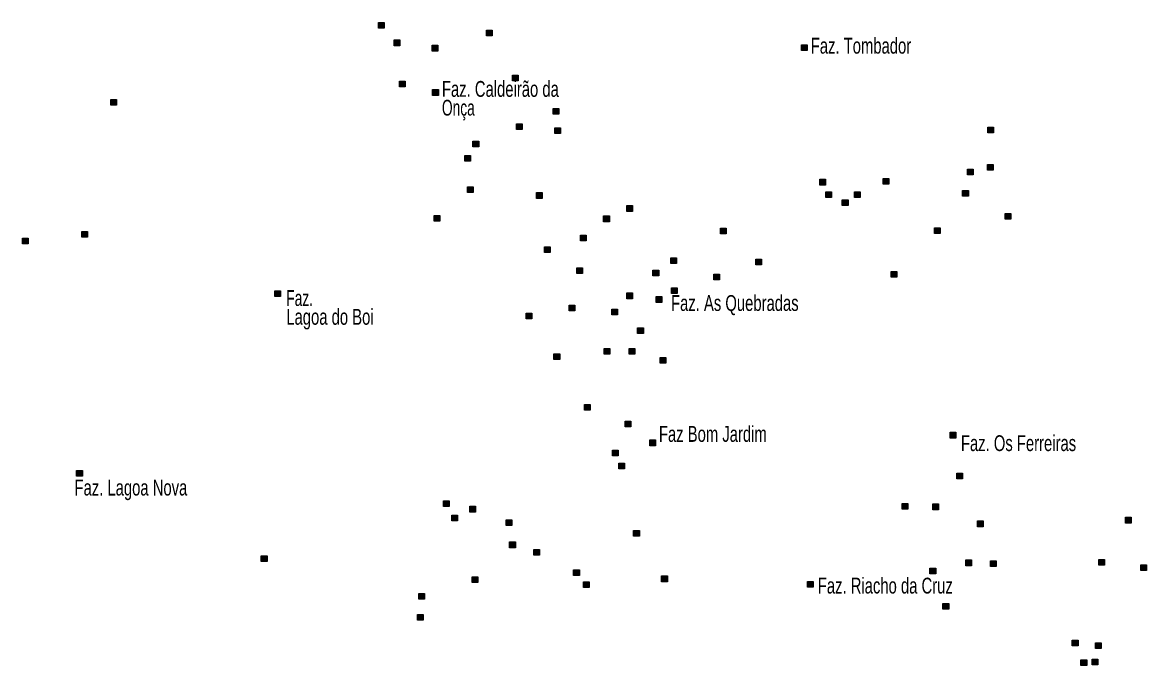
# Model space of a CAD drawing. Extents: x 445.4 to 500, y 8728.7 to 8784.
# Drawn here: x 458.24 to 469.61, y 8757.95 to 8764.45 of the extents above; entities that cross this region are included whole.
import ezdxf
from ezdxf.enums import TextEntityAlignment as Align

# ---------------------------------------------------------------- set-up
doc = ezdxf.new("R2010")
doc.units = 0
doc.header["$LTSCALE"] = 0.064
doc.layers.add('2', color=7, linetype='Continuous', lineweight=25)
doc.layers.add('61', color=7, linetype='Continuous')

msp = doc.modelspace()

# ---------------------------------------------------------------- hatches: boundary and pattern name
at = {"layer": '2'}
for points in [[(461.8411, 8764.4531), (461.8991, 8764.4531), (461.8991, 8764.3951), (461.8411, 8764.3951)], [(462.9316, 8764.3761), (462.9896, 8764.3761), (462.9896, 8764.3181), (462.9316, 8764.3181)], [(461.9995, 8764.2765), (462.0575, 8764.2765), (462.0575, 8764.2185), (461.9995, 8764.2185)], [(462.3841, 8764.2222), (462.4421, 8764.2222), (462.4421, 8764.1642), (462.3841, 8764.1642)], [(466.1186, 8764.2285), (466.1766, 8764.2285), (466.1766, 8764.1705), (466.1186, 8764.1705)], [(462.0538, 8763.86), (462.1118, 8763.86), (462.1118, 8763.802), (462.0538, 8763.802)], [(463.196, 8763.9203), (463.254, 8763.9203), (463.254, 8763.8623), (463.196, 8763.8623)], [(462.3886, 8763.774), (462.4466, 8763.774), (462.4466, 8763.716), (462.3886, 8763.716)], [(459.1351, 8763.6754), (459.1931, 8763.6754), (459.1931, 8763.6174), (459.1351, 8763.6174)], [(463.6059, 8763.5838), (463.6639, 8763.5838), (463.6639, 8763.5258), (463.6059, 8763.5258)], [(463.2348, 8763.4299), (463.2928, 8763.4299), (463.2928, 8763.3719), (463.2348, 8763.3719)], [(463.624, 8763.3891), (463.682, 8763.3891), (463.682, 8763.3311), (463.624, 8763.3311)], [(468.0027, 8763.3944), (468.0607, 8763.3944), (468.0607, 8763.3364), (468.0027, 8763.3364)], [(462.7959, 8763.2533), (462.8539, 8763.2533), (462.8539, 8763.1953), (462.7959, 8763.1953)], [(462.7144, 8763.1084), (462.7724, 8763.1084), (462.7724, 8763.0504), (462.7144, 8763.0504)], [(467.7974, 8762.9716), (467.8554, 8762.9716), (467.8554, 8762.9136), (467.7974, 8762.9136)], [(467.9989, 8763.0171), (468.0569, 8763.0171), (468.0569, 8762.9591), (467.9989, 8762.9591)], [(466.3042, 8762.8675), (466.3622, 8762.8675), (466.3622, 8762.8095), (466.3042, 8762.8095)], [(466.9422, 8762.8765), (467.0002, 8762.8765), (467.0002, 8762.8185), (466.9422, 8762.8185)], [(462.7416, 8762.7915), (462.7996, 8762.7915), (462.7996, 8762.7335), (462.7416, 8762.7335)], [(463.4384, 8762.7327), (463.4964, 8762.7327), (463.4964, 8762.6747), (463.4384, 8762.6747)], [(466.363, 8762.7407), (466.421, 8762.7407), (466.421, 8762.6827), (466.363, 8762.6827)], [(466.6526, 8762.7407), (466.7106, 8762.7407), (466.7106, 8762.6827), (466.6526, 8762.6827)], [(467.7476, 8762.7543), (467.8056, 8762.7543), (467.8056, 8762.6963), (467.7476, 8762.6963)], [(464.3525, 8762.6014), (464.4105, 8762.6014), (464.4105, 8762.5434), (464.3525, 8762.5434)], [(466.5304, 8762.6592), (466.5884, 8762.6592), (466.5884, 8762.6012), (466.5304, 8762.6012)], [(462.4022, 8762.5018), (462.4602, 8762.5018), (462.4602, 8762.4438), (462.4022, 8762.4438)], [(464.1172, 8762.4972), (464.1752, 8762.4972), (464.1752, 8762.4392), (464.1172, 8762.4392)], [(468.1775, 8762.5234), (468.2355, 8762.5234), (468.2355, 8762.4654), (468.1775, 8762.4654)], [(465.2996, 8762.374), (465.3576, 8762.374), (465.3576, 8762.316), (465.2996, 8762.316)], [(467.4626, 8762.3785), (467.5206, 8762.3785), (467.5206, 8762.3205), (467.4626, 8762.3205)], [(458.2411, 8762.2739), (458.2991, 8762.2739), (458.2991, 8762.2159), (458.2411, 8762.2159)], [(458.841, 8762.3398), (458.899, 8762.3398), (458.899, 8762.2818), (458.841, 8762.2818)], [(463.8819, 8762.3025), (463.9399, 8762.3025), (463.9399, 8762.2445), (463.8819, 8762.2445)], [(463.519, 8762.1861), (463.577, 8762.1861), (463.577, 8762.1281), (463.519, 8762.1281)], [(464.7961, 8762.0752), (464.8541, 8762.0752), (464.8541, 8762.0172), (464.7961, 8762.0172)], [(465.6571, 8762.0616), (465.7151, 8762.0616), (465.7151, 8762.0036), (465.6571, 8762.0036)], [(463.8457, 8761.972), (463.9037, 8761.972), (463.9037, 8761.914), (463.8457, 8761.914)], [(464.6163, 8761.9484), (464.6743, 8761.9484), (464.6743, 8761.8904), (464.6163, 8761.8904)], [(465.2317, 8761.9077), (465.2897, 8761.9077), (465.2897, 8761.8497), (465.2317, 8761.8497)], [(467.0236, 8761.9348), (467.0816, 8761.9348), (467.0816, 8761.8768), (467.0236, 8761.8768)], [(460.7913, 8761.7411), (460.8493, 8761.7411), (460.8493, 8761.6831), (460.7913, 8761.6831)], [(464.3525, 8761.7185), (464.4105, 8761.7185), (464.4105, 8761.6605), (464.3525, 8761.6605)], [(464.648, 8761.6813), (464.706, 8761.6813), (464.706, 8761.6233), (464.648, 8761.6233)], [(464.8019, 8761.7719), (464.8599, 8761.7719), (464.8599, 8761.7139), (464.8019, 8761.7139)], [(463.7688, 8761.5963), (463.8268, 8761.5963), (463.8268, 8761.5383), (463.7688, 8761.5383)], [(464.1986, 8761.5555), (464.2566, 8761.5555), (464.2566, 8761.4975), (464.1986, 8761.4975)], [(463.3344, 8761.5148), (463.3924, 8761.5148), (463.3924, 8761.4568), (463.3344, 8761.4568)], [(464.4611, 8761.3654), (464.5191, 8761.3654), (464.5191, 8761.3074), (464.4611, 8761.3074)], [(463.6149, 8761.1028), (463.6729, 8761.1028), (463.6729, 8761.0448), (463.6149, 8761.0448)], [(464.1217, 8761.1571), (464.1797, 8761.1571), (464.1797, 8761.0991), (464.1217, 8761.0991)], [(464.3751, 8761.1571), (464.4331, 8761.1571), (464.4331, 8761.0991), (464.3751, 8761.0991)], [(464.6891, 8761.0658), (464.7471, 8761.0658), (464.7471, 8761.0078), (464.6891, 8761.0078)], [(463.9226, 8760.5912), (463.9806, 8760.5912), (463.9806, 8760.5332), (463.9226, 8760.5332)], [(464.3344, 8760.4237), (464.3924, 8760.4237), (464.3924, 8760.3657), (464.3344, 8760.3657)], [(467.6209, 8760.3095), (467.6789, 8760.3095), (467.6789, 8760.2515), (467.6209, 8760.2515)], [(464.5847, 8760.2325), (464.6427, 8760.2325), (464.6427, 8760.1745), (464.5847, 8760.1745)], [(464.2077, 8760.1294), (464.2657, 8760.1294), (464.2657, 8760.0714), (464.2077, 8760.0714)], [(464.271, 8759.9981), (464.329, 8759.9981), (464.329, 8759.9401), (464.271, 8759.9401)], [(458.7884, 8759.9239), (458.8464, 8759.9239), (458.8464, 8759.8659), (458.7884, 8759.8659)], [(467.6888, 8759.8975), (467.7468, 8759.8975), (467.7468, 8759.8395), (467.6888, 8759.8395)], [(462.4972, 8759.6178), (462.5552, 8759.6178), (462.5552, 8759.5598), (462.4972, 8759.5598)], [(462.7642, 8759.5617), (462.8222, 8759.5617), (462.8222, 8759.5037), (462.7642, 8759.5037)], [(467.1368, 8759.5896), (467.1948, 8759.5896), (467.1948, 8759.5316), (467.1368, 8759.5316)], [(467.4445, 8759.5851), (467.5025, 8759.5851), (467.5025, 8759.5271), (467.4445, 8759.5271)], [(462.5832, 8759.4711), (462.6412, 8759.4711), (462.6412, 8759.4131), (462.5832, 8759.4131)], [(463.1307, 8759.4259), (463.1887, 8759.4259), (463.1887, 8759.3679), (463.1307, 8759.3679)], [(467.897, 8759.4131), (467.955, 8759.4131), (467.955, 8759.3551), (467.897, 8759.3551)], [(469.3948, 8759.4503), (469.4528, 8759.4503), (469.4528, 8759.3923), (469.3948, 8759.3923)], [(464.4204, 8759.3172), (464.4784, 8759.3172), (464.4784, 8759.2592), (464.4204, 8759.2592)], [(463.1669, 8759.2012), (463.2249, 8759.2012), (463.2249, 8759.1432), (463.1669, 8759.1432)], [(460.6556, 8759.0609), (460.7136, 8759.0609), (460.7136, 8759.0029), (460.6556, 8759.0029)], [(463.4113, 8759.1243), (463.4693, 8759.1243), (463.4693, 8759.0663), (463.4113, 8759.0663)], [(467.4173, 8758.9377), (467.4753, 8758.9377), (467.4753, 8758.8797), (467.4173, 8758.8797)], [(467.7793, 8759.0192), (467.8373, 8759.0192), (467.8373, 8758.9612), (467.7793, 8758.9612)], [(468.0282, 8759.0101), (468.0862, 8759.0101), (468.0862, 8758.9521), (468.0282, 8758.9521)], [(469.1233, 8759.0247), (469.1813, 8759.0247), (469.1813, 8758.9667), (469.1233, 8758.9667)], [(469.5486, 8758.9703), (469.6066, 8758.9703), (469.6066, 8758.9123), (469.5486, 8758.9123)], [(462.7868, 8758.8481), (462.8448, 8758.8481), (462.8448, 8758.7901), (462.7868, 8758.7901)], [(463.814, 8758.9205), (463.872, 8758.9205), (463.872, 8758.8625), (463.814, 8758.8625)], [(464.7041, 8758.8572), (464.7621, 8758.8572), (464.7621, 8758.7992), (464.7041, 8758.7992)], [(463.9136, 8758.7983), (463.9716, 8758.7983), (463.9716, 8758.7403), (463.9136, 8758.7403)], [(466.1775, 8758.8018), (466.2355, 8758.8018), (466.2355, 8758.7438), (466.1775, 8758.7438)], [(462.2484, 8758.6806), (462.3064, 8758.6806), (462.3064, 8758.6226), (462.2484, 8758.6226)], [(467.5485, 8758.58), (467.6065, 8758.58), (467.6065, 8758.522), (467.5485, 8758.522)], [(462.2348, 8758.4678), (462.2928, 8758.4678), (462.2928, 8758.4098), (462.2348, 8758.4098)], [(468.8563, 8758.2097), (468.9143, 8758.2097), (468.9143, 8758.1517), (468.8563, 8758.1517)], [(469.0916, 8758.1826), (469.1496, 8758.1826), (469.1496, 8758.1246), (469.0916, 8758.1246)], [(468.9439, 8758.0098), (469.0019, 8758.0098), (469.0019, 8757.9518), (468.9439, 8757.9518)], [(469.0554, 8758.0151), (469.1134, 8758.0151), (469.1134, 8757.9571), (469.0554, 8757.9571)]]:
    msp.add_hatch(color=256, dxfattribs=at).paths.add_polyline_path(points)

# ---------------------------------------------------------------- linework, layer by layer
for points in [[(461.8411, 8764.4531), (461.8991, 8764.4531), (461.8991, 8764.3951), (461.8411, 8764.3951)], [(462.9316, 8764.3761), (462.9896, 8764.3761), (462.9896, 8764.3181), (462.9316, 8764.3181)], [(461.9995, 8764.2765), (462.0575, 8764.2765), (462.0575, 8764.2185), (461.9995, 8764.2185)], [(462.3841, 8764.2222), (462.4421, 8764.2222), (462.4421, 8764.1642), (462.3841, 8764.1642)], [(466.1186, 8764.2285), (466.1766, 8764.2285), (466.1766, 8764.1705), (466.1186, 8764.1705)], [(462.0538, 8763.86), (462.1118, 8763.86), (462.1118, 8763.802), (462.0538, 8763.802)], [(463.196, 8763.9203), (463.254, 8763.9203), (463.254, 8763.8623), (463.196, 8763.8623)], [(462.3886, 8763.774), (462.4466, 8763.774), (462.4466, 8763.716), (462.3886, 8763.716)], [(459.1351, 8763.6754), (459.1931, 8763.6754), (459.1931, 8763.6174), (459.1351, 8763.6174)], [(463.6059, 8763.5838), (463.6639, 8763.5838), (463.6639, 8763.5258), (463.6059, 8763.5258)], [(463.2348, 8763.4299), (463.2928, 8763.4299), (463.2928, 8763.3719), (463.2348, 8763.3719)], [(463.624, 8763.3891), (463.682, 8763.3891), (463.682, 8763.3311), (463.624, 8763.3311)], [(468.0027, 8763.3944), (468.0607, 8763.3944), (468.0607, 8763.3364), (468.0027, 8763.3364)], [(462.7959, 8763.2533), (462.8539, 8763.2533), (462.8539, 8763.1953), (462.7959, 8763.1953)], [(462.7144, 8763.1084), (462.7724, 8763.1084), (462.7724, 8763.0504), (462.7144, 8763.0504)], [(467.7974, 8762.9716), (467.8554, 8762.9716), (467.8554, 8762.9136), (467.7974, 8762.9136)], [(467.9989, 8763.0171), (468.0569, 8763.0171), (468.0569, 8762.9591), (467.9989, 8762.9591)], [(466.3042, 8762.8675), (466.3622, 8762.8675), (466.3622, 8762.8095), (466.3042, 8762.8095)], [(466.9422, 8762.8765), (467.0002, 8762.8765), (467.0002, 8762.8185), (466.9422, 8762.8185)], [(462.7416, 8762.7915), (462.7996, 8762.7915), (462.7996, 8762.7335), (462.7416, 8762.7335)], [(463.4384, 8762.7327), (463.4964, 8762.7327), (463.4964, 8762.6747), (463.4384, 8762.6747)], [(466.363, 8762.7407), (466.421, 8762.7407), (466.421, 8762.6827), (466.363, 8762.6827)], [(466.6526, 8762.7407), (466.7106, 8762.7407), (466.7106, 8762.6827), (466.6526, 8762.6827)], [(467.7476, 8762.7543), (467.8056, 8762.7543), (467.8056, 8762.6963), (467.7476, 8762.6963)], [(464.3525, 8762.6014), (464.4105, 8762.6014), (464.4105, 8762.5434), (464.3525, 8762.5434)], [(466.5304, 8762.6592), (466.5884, 8762.6592), (466.5884, 8762.6012), (466.5304, 8762.6012)], [(462.4022, 8762.5018), (462.4602, 8762.5018), (462.4602, 8762.4438), (462.4022, 8762.4438)], [(464.1172, 8762.4972), (464.1752, 8762.4972), (464.1752, 8762.4392), (464.1172, 8762.4392)], [(468.1775, 8762.5234), (468.2355, 8762.5234), (468.2355, 8762.4654), (468.1775, 8762.4654)], [(465.2996, 8762.374), (465.3576, 8762.374), (465.3576, 8762.316), (465.2996, 8762.316)], [(467.4626, 8762.3785), (467.5206, 8762.3785), (467.5206, 8762.3205), (467.4626, 8762.3205)], [(458.2411, 8762.2739), (458.2991, 8762.2739), (458.2991, 8762.2159), (458.2411, 8762.2159)], [(458.841, 8762.3398), (458.899, 8762.3398), (458.899, 8762.2818), (458.841, 8762.2818)], [(463.8819, 8762.3025), (463.9399, 8762.3025), (463.9399, 8762.2445), (463.8819, 8762.2445)], [(463.519, 8762.1861), (463.577, 8762.1861), (463.577, 8762.1281), (463.519, 8762.1281)], [(464.7961, 8762.0752), (464.8541, 8762.0752), (464.8541, 8762.0172), (464.7961, 8762.0172)], [(465.6571, 8762.0616), (465.7151, 8762.0616), (465.7151, 8762.0036), (465.6571, 8762.0036)], [(463.8457, 8761.972), (463.9037, 8761.972), (463.9037, 8761.914), (463.8457, 8761.914)], [(464.6163, 8761.9484), (464.6743, 8761.9484), (464.6743, 8761.8904), (464.6163, 8761.8904)], [(465.2317, 8761.9077), (465.2897, 8761.9077), (465.2897, 8761.8497), (465.2317, 8761.8497)], [(467.0236, 8761.9348), (467.0816, 8761.9348), (467.0816, 8761.8768), (467.0236, 8761.8768)], [(460.7913, 8761.7411), (460.8493, 8761.7411), (460.8493, 8761.6831), (460.7913, 8761.6831)], [(464.3525, 8761.7185), (464.4105, 8761.7185), (464.4105, 8761.6605), (464.3525, 8761.6605)], [(464.648, 8761.6813), (464.706, 8761.6813), (464.706, 8761.6233), (464.648, 8761.6233)], [(464.8019, 8761.7719), (464.8599, 8761.7719), (464.8599, 8761.7139), (464.8019, 8761.7139)], [(463.7688, 8761.5963), (463.8268, 8761.5963), (463.8268, 8761.5383), (463.7688, 8761.5383)], [(464.1986, 8761.5555), (464.2566, 8761.5555), (464.2566, 8761.4975), (464.1986, 8761.4975)], [(463.3344, 8761.5148), (463.3924, 8761.5148), (463.3924, 8761.4568), (463.3344, 8761.4568)], [(464.4611, 8761.3654), (464.5191, 8761.3654), (464.5191, 8761.3074), (464.4611, 8761.3074)], [(463.6149, 8761.1028), (463.6729, 8761.1028), (463.6729, 8761.0448), (463.6149, 8761.0448)], [(464.1217, 8761.1571), (464.1797, 8761.1571), (464.1797, 8761.0991), (464.1217, 8761.0991)], [(464.3751, 8761.1571), (464.4331, 8761.1571), (464.4331, 8761.0991), (464.3751, 8761.0991)], [(464.6891, 8761.0658), (464.7471, 8761.0658), (464.7471, 8761.0078), (464.6891, 8761.0078)], [(463.9226, 8760.5912), (463.9806, 8760.5912), (463.9806, 8760.5332), (463.9226, 8760.5332)], [(464.3344, 8760.4237), (464.3924, 8760.4237), (464.3924, 8760.3657), (464.3344, 8760.3657)], [(467.6209, 8760.3095), (467.6789, 8760.3095), (467.6789, 8760.2515), (467.6209, 8760.2515)], [(464.5847, 8760.2325), (464.6427, 8760.2325), (464.6427, 8760.1745), (464.5847, 8760.1745)], [(464.2077, 8760.1294), (464.2657, 8760.1294), (464.2657, 8760.0714), (464.2077, 8760.0714)], [(464.271, 8759.9981), (464.329, 8759.9981), (464.329, 8759.9401), (464.271, 8759.9401)], [(458.7884, 8759.9239), (458.8464, 8759.9239), (458.8464, 8759.8659), (458.7884, 8759.8659)], [(467.6888, 8759.8975), (467.7468, 8759.8975), (467.7468, 8759.8395), (467.6888, 8759.8395)], [(462.4972, 8759.6178), (462.5552, 8759.6178), (462.5552, 8759.5598), (462.4972, 8759.5598)], [(462.7642, 8759.5617), (462.8222, 8759.5617), (462.8222, 8759.5037), (462.7642, 8759.5037)], [(467.1368, 8759.5896), (467.1948, 8759.5896), (467.1948, 8759.5316), (467.1368, 8759.5316)], [(467.4445, 8759.5851), (467.5025, 8759.5851), (467.5025, 8759.5271), (467.4445, 8759.5271)], [(462.5832, 8759.4711), (462.6412, 8759.4711), (462.6412, 8759.4131), (462.5832, 8759.4131)], [(463.1307, 8759.4259), (463.1887, 8759.4259), (463.1887, 8759.3679), (463.1307, 8759.3679)], [(467.897, 8759.4131), (467.955, 8759.4131), (467.955, 8759.3551), (467.897, 8759.3551)], [(469.3948, 8759.4503), (469.4528, 8759.4503), (469.4528, 8759.3923), (469.3948, 8759.3923)], [(464.4204, 8759.3172), (464.4784, 8759.3172), (464.4784, 8759.2592), (464.4204, 8759.2592)], [(463.1669, 8759.2012), (463.2249, 8759.2012), (463.2249, 8759.1432), (463.1669, 8759.1432)], [(460.6556, 8759.0609), (460.7136, 8759.0609), (460.7136, 8759.0029), (460.6556, 8759.0029)], [(463.4113, 8759.1243), (463.4693, 8759.1243), (463.4693, 8759.0663), (463.4113, 8759.0663)], [(467.4173, 8758.9377), (467.4753, 8758.9377), (467.4753, 8758.8797), (467.4173, 8758.8797)], [(467.7793, 8759.0192), (467.8373, 8759.0192), (467.8373, 8758.9612), (467.7793, 8758.9612)], [(468.0282, 8759.0101), (468.0862, 8759.0101), (468.0862, 8758.9521), (468.0282, 8758.9521)], [(469.1233, 8759.0247), (469.1813, 8759.0247), (469.1813, 8758.9667), (469.1233, 8758.9667)], [(469.5486, 8758.9703), (469.6066, 8758.9703), (469.6066, 8758.9123), (469.5486, 8758.9123)], [(462.7868, 8758.8481), (462.8448, 8758.8481), (462.8448, 8758.7901), (462.7868, 8758.7901)], [(463.814, 8758.9205), (463.872, 8758.9205), (463.872, 8758.8625), (463.814, 8758.8625)], [(464.7041, 8758.8572), (464.7621, 8758.8572), (464.7621, 8758.7992), (464.7041, 8758.7992)], [(463.9136, 8758.7983), (463.9716, 8758.7983), (463.9716, 8758.7403), (463.9136, 8758.7403)], [(466.1775, 8758.8018), (466.2355, 8758.8018), (466.2355, 8758.7438), (466.1775, 8758.7438)], [(462.2484, 8758.6806), (462.3064, 8758.6806), (462.3064, 8758.6226), (462.2484, 8758.6226)], [(467.5485, 8758.58), (467.6065, 8758.58), (467.6065, 8758.522), (467.5485, 8758.522)], [(462.2348, 8758.4678), (462.2928, 8758.4678), (462.2928, 8758.4098), (462.2348, 8758.4098)], [(468.8563, 8758.2097), (468.9143, 8758.2097), (468.9143, 8758.1517), (468.8563, 8758.1517)], [(469.0916, 8758.1826), (469.1496, 8758.1826), (469.1496, 8758.1246), (469.0916, 8758.1246)], [(468.9439, 8758.0098), (469.0019, 8758.0098), (469.0019, 8757.9518), (468.9439, 8757.9518)], [(469.0554, 8758.0151), (469.1134, 8758.0151), (469.1134, 8757.9571), (469.0554, 8757.9571)]]:
    msp.add_lwpolyline(points, close=True, dxfattribs=at)

# ---------------------------------------------------------------- texts
at = {"layer": '61'}
for s, width, p in [('Faz. Tombador', 0.7, (466.2116, 8764.1382)), ('Faz. Caldeirão da', 0.7, (462.4822, 8763.7014)), ('Onça', 0.65, (462.4822, 8763.5114)), ('Faz.', 0.65, (460.9088, 8761.5873)), ('Faz. As Quebradas', 0.7, (464.7988, 8761.5369)), ('Lagoa do Boi', 0.7, (460.9088, 8761.3973)), ('Faz Bom Jardim', 0.7, (464.6765, 8760.2132)), ('Faz. Os Ferreiras', 0.7, (467.7298, 8760.1198)), ('Faz. Riacho da Cruz', 0.7, (466.2828, 8758.6797))]:
    msp.add_text(s, height=0.16, dxfattribs=dict(at, width=width)).set_placement(p)
at = {"layer": '61', "width": 0.7}
msp.add_text('            Faz. Lagoa Nova', height=0.16, dxfattribs=at).set_placement((459.9077, 8759.6707), align=Align.RIGHT)

doc.saveas('drawing.dxf')
